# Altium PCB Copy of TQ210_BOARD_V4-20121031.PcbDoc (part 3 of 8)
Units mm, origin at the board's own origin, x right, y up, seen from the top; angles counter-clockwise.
Board outline 191.2 x 131.27 mm, 2 copper layers (TopLayer, BottomLayer); 362 components, 455 nets, 1594 pads, 630 vias.
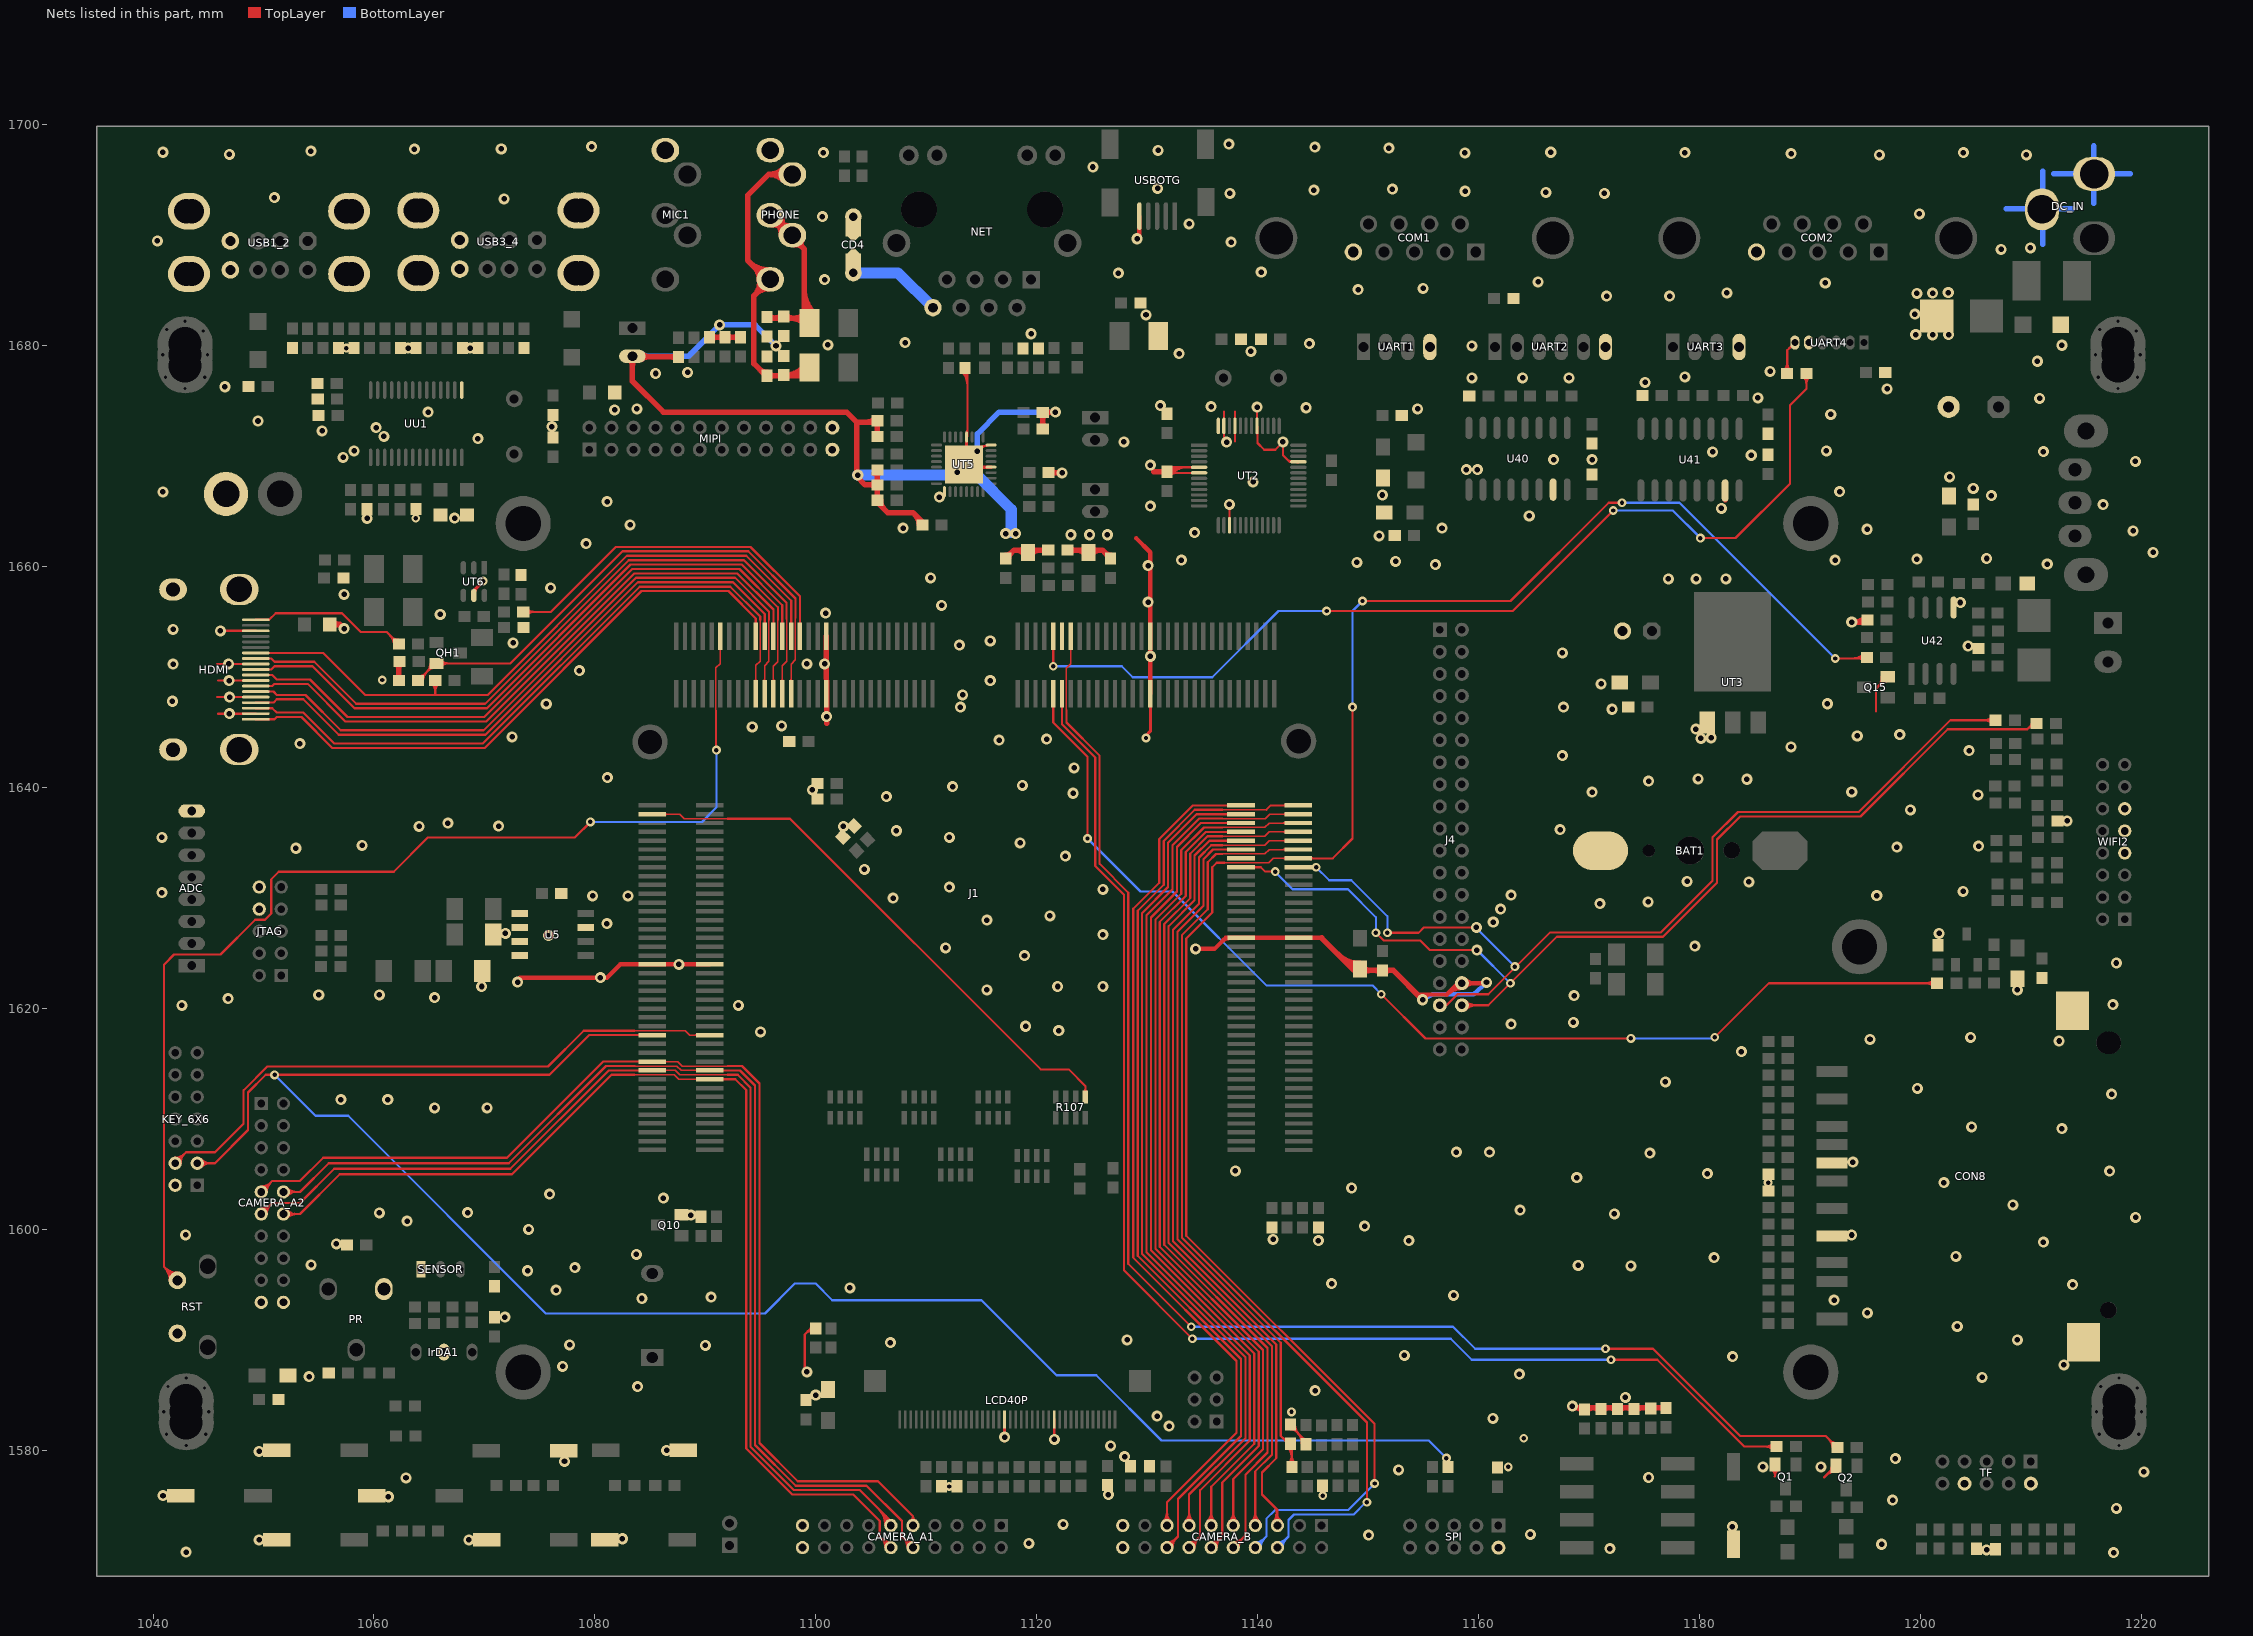
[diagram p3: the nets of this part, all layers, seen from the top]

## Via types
v1: diameter 1, hole 0.5, TopLayer to BottomLayer, 458 vias
v2: diameter 0.8, hole 0.4, TopLayer to BottomLayer, 172 vias

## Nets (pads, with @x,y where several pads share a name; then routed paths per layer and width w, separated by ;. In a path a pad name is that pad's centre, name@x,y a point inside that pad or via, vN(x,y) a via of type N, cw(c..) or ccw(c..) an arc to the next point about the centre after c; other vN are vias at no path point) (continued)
CAMDATA4: CAMERA_A1.12 CAMERA_A2.12 J1.18 | length 103.8
  TopLayer w0.135: 1083.6,1614 1087.2,1614 1087.6,1613.6 J1.18@1090.4,1613.6
  TopLayer w0.2: CAMERA_A2.12@1051.8,1601.4 1053.3,1601.4 1056.9,1605 1072.5,1605 1081.5,1614 1083.6,1614 ; CAMERA_A2.12@1052.012,1601.188 cw(c1052.524,1600.676) 1052.524,1601.4 cw(c1052.524,1602.124) CAMERA_A2.12@1052.012,1601.612 ; CAMERA_A2.12@1052.154,1601.046 cw(c1053.007,1600.193) 1053.007,1601.4 cw(c1053.007,1602.607) CAMERA_A2.12@1052.154,1601.754 ; J1.18@1090.4,1613.6 1092.719,1613.6 1093.7,1612.619 1093.7,1580.163 1097.863,1576 1103.4,1576 1105.8,1573.6 1105.8,1572.2 CAMERA_A1.12@1106.8,1571.2 ; CAMERA_A1.12@1106.3,1571.2 ccw(c1105.093,1571.2) 1105.946,1572.054 ccw(c1106.8,1572.907) CAMERA_A1.12@1106.8,1571.7 ; CAMERA_A1.12@1106.5,1571.2 ccw(c1105.776,1571.2) 1106.288,1571.712 ccw(c1106.8,1572.224) CAMERA_A1.12@1106.8,1571.5
CAMDATA5: CAMERA_A1.11 CAMERA_A2.11 J1.19 | length 105.7
  TopLayer w0.135: J1.19@1085.2,1614.4 1087.3,1614.4 1087.7,1614 1092,1614
  TopLayer w0.2: CAMERA_A2.11@1049.8,1601.4 1050.8,1602.4 1053.3,1602.4 1056.4,1605.5 1072.35,1605.5 1081.25,1614.4 J1.19@1085.2,1614.4 ; CAMERA_A2.11@1049.8,1601.7 ccw(c1049.8,1602.424) 1050.312,1601.912 ccw(c1050.824,1601.4) CAMERA_A2.11@1050.1,1601.4 ; CAMERA_A2.11@1049.8,1601.9 ccw(c1049.8,1603.107) 1050.654,1602.254 ccw(c1051.507,1601.4) CAMERA_A2.11@1050.3,1601.4 ; 1092,1614 1092.929,1614 1094.1,1612.829 1094.1,1580.328 1098.028,1576.4 1104,1576.4 1106.8,1573.6 CAMERA_A1.11@1106.8,1573.2 ; 1105.664,1574.736 cw(c1104.127,1573.2) CAMERA_A1.11@1106.3,1573.2 ; 1106.005,1574.395 cw(c1104.81,1573.2) CAMERA_A1.11@1106.5,1573.2 ; 1106.346,1574.054 cw(c1105.493,1573.2) CAMERA_A1.11@1106.7,1573.2
CAMDATA6: CAMERA_A1.10 CAMERA_A2.10 J1.20 | length 105.7
  TopLayer w0.135: 1083.6,1614.8 1087.4,1614.8 1087.8,1614.4 J1.20@1090.4,1614.4
  TopLayer w0.2: CAMERA_A2.10@1051.8,1603.4 1053.3,1603.4 1055.9,1606 1072.2,1606 1081,1614.8 1083.6,1614.8 ; CAMERA_A2.10@1052.012,1603.188 cw(c1052.524,1602.676) 1052.524,1603.4 cw(c1052.524,1604.124) CAMERA_A2.10@1052.012,1603.612 ; CAMERA_A2.10@1052.154,1603.046 cw(c1053.007,1602.193) 1053.007,1603.4 cw(c1053.007,1604.607) CAMERA_A2.10@1052.154,1603.754 ; J1.20@1090.4,1614.4 1093.138,1614.4 1094.5,1613.038 1094.5,1580.494 1098.194,1576.8 1104.6,1576.8 1107.8,1573.6 1107.8,1572.2 CAMERA_A1.10@1108.8,1571.2 ; CAMERA_A1.10@1108.3,1571.2 ccw(c1107.093,1571.2) 1107.946,1572.054 ccw(c1108.8,1572.907) CAMERA_A1.10@1108.8,1571.7 ; CAMERA_A1.10@1108.5,1571.2 ccw(c1107.776,1571.2) 1108.288,1571.712 ccw(c1108.8,1572.224) CAMERA_A1.10@1108.8,1571.5
CAMDATA7: CAMERA_A1.9 CAMERA_A2.9 J1.21 | length 104.8
  TopLayer w0.135: J1.21@1085.2,1615.2 1087.5,1615.2 1087.9,1614.8 1092,1614.8
  TopLayer w0.2: CAMERA_A2.9@1049.8,1603.4 1050.8,1604.4 1053.3,1604.4 1055.4,1606.5 1072.05,1606.5 1080.75,1615.2 J1.21@1085.2,1615.2 ; CAMERA_A2.9@1049.8,1603.7 ccw(c1049.8,1604.424) 1050.312,1603.912 ccw(c1050.824,1603.4) CAMERA_A2.9@1050.1,1603.4 ; CAMERA_A2.9@1049.8,1603.9 ccw(c1049.8,1605.107) 1050.654,1604.254 ccw(c1051.507,1603.4) CAMERA_A2.9@1050.3,1603.4 ; 1092,1614.8 1093.323,1614.8 1094.9,1613.223 1094.9,1580.66 1098.36,1577.2 1105.634,1577.2 1108.8,1574.034 ; CAMERA_A1.9@1108.564,1573.641 ccw(c1108.354,1574.034) 1108.8,1574.034 ; CAMERA_A1.9@1108.8,1573.2 1108.8,1574.034 ; CAMERA_A1.9@1109.036,1573.641 cw(c1109.246,1574.034) 1108.8,1574.034
DAC_OUT0: J1.109 RT64.1 | length 34.5
  TopLayer w0.2: RT64.1@1073.51,1655.911 1076,1655.911 1081.889,1661.8 1094.1,1661.8 1098.575,1657.325 J1.109@1098.575,1653.687 ; RT64.1@1073.843,1655.629 cw(c1074.526,1654.946) 1074.526,1655.911 cw(c1074.526,1656.877) RT64.1@1073.843,1656.194
EXT_NRESET: J1.91 RST.2 | length 107
  TopLayer w0.135: 1090.965,1647.016 1090.965,1650.837 1091.365,1651.236 J1.91@1091.365,1653.697
  TopLayer w0.2: RST.2@1041.5,1595.4 ccw(c1039.81,1595.4) 1041.005,1596.595 ccw(c1042.2,1597.79) RST.2@1042.2,1596.1 ; RST.2@1041.7,1595.4 ccw(c1040.493,1595.4) 1041.346,1596.254 ccw(c1042.2,1597.107) RST.2@1042.2,1595.9 ; RST.2@1042.2,1595.4 1041,1596.6 1041,1624 1041.9,1624.9 1046.1,1624.9 1049.238,1628.038 1050.138,1628.038 1050.7,1628.6 1050.7,1631.7 1051.385,1632.385 1061.785,1632.385 1064.9,1635.5 1078.2,1635.5 v2(1079.6,1636.9) ; v2@1090.981,1643.419 1090.981,1647
  BottomLayer w0.2: v2(1079.6,1636.9) 1089.703,1636.9 1091,1638.197 v2(1091,1643.4)
GND: ADC.8 BAT1.2 C1.2 C3.2 C5.2 C6.2 C8.2 C9.2 C10.2 C11.2 C12.2 C15.2 C17.2 C21.2 C22.2 C23.2 C101.2 C102.2 C105.2 C106.2 C107.2 C111.2 C201.2 C202.2 C203.2 C205.2 C207.1 C208.1 C210.2 C211.1 C212.1 C403.2 C404.2 C405.2 C413.2 C414.2 C415.2 C423.1 C501.2 C513.2 C517.2 C518.2 CAMERA_A1.19 CAMERA_A1.20 CAMERA_A2.19 CAMERA_A2.20 CAMERA_B.19 CAMERA_B.20 CD1.2 CD2.2 CD4.2 CL1.2 CL2.2 CL3.2 CL4.2 CL5.2 CM1.2 CM2.2 CM3.2 CM4.2 CMB1.2 CMB2.2 COM1.5 COM2.5 CON8.3 CON8.6 CON8.13 CON8.14 CS1.2 CS2.2 CT6.1 CU1.2 CU2.2 CU3.1 CU4.2 CU5.2 CU6.2 CU7.2 CU10.1 CU11.1 CV1.2 CW1.2 CW2.1 CW4.1 CW5.2 D6.1 D8.1 D101.1 DC_IN.2 DC_IN.3 HDMI.2 HDMI.5 HDMI.8 HDMI.11 HDMI.17 HDMI.20 HDMI.21 HDMI.22 HDMI.23 IrDA1.2 J1.43 J1.44 J1.115 J1.116 J1.171 J1.172 J1.231 J1.232 J4.34 JTAG.8 JTAG.10 KEY1.2 KEY2.2 KEY3.2 KEY4.2 KEY5.2 KEY6.2 KEY7.2 KEY8.2 KEY_6X6.2 KEYON.2 L502.1 LCD40P.20 LCD40P.29 MIPI.23 MIPI.24 POWER.2 PR.1 Q1.E Q2.E Q10.E Q15.E R31.2 R204.2 R424.2 RF2.2 RH13.1 RH14.2 RM6.2 RM21.1 RMB6.2 RMB21.1 RO1.1 RO2.2 RO3.2 RO4.2 RO5.1 RO6.1 RST.1 RT1.2 RT3.1 RT63.2 RT65.2 RU3.1 RU4.1 RU7.1 RU8.1 RU11.1 RU12.1 RU15.1 RU16.1 RU17.2 RU21.2 SENSOR.1 SPI.2 TF.2 TF.8 TVOUT.2 U5.1 U5.2 U5.3 U5.4 U5.7 U40.15 U41.15 U42.5 UART1.4 UART2.6 UART3.4 UART4.5 USB1_2.4 USB1_2.8 USB1_2.9 USB1_2.10 USB1_2.11 USB1_2.12 USB3_4.4 USB3_4.8 USB3_4.9 USB3_4.10 USB3_4.11 USB3_4.12 USBOTG.5 UT2.5 UT2.6 UT2.15 UT2.33 UT2.41 UT2.45 UT2.47 UT2.48 UT3.1 UT5.9 UT6.5 UU1.1 WIFI2.7 WIFI2.9 WIFI2.11 | length 238.1
  TopLayer w0.2: 1045.8,1648.2 HDMI.5@1049.3,1648.2 ; 1045.8,1651.2 HDMI.11@1049.3,1651.2 ; v1@1045.8,1654.2 HDMI.17@1049.3,1654.2 ; 1045.9,1646.7 HDMI.2@1049.3,1646.7 ; 1045.9,1649.7 HDMI.8@1049.3,1649.7 ; RH13.1@1062.252,1651.359 RH13.1@1062.298,1651.405 ; UT6.5@1069.045,1657.845 UT6.5@1069.045,1657.412 UT6.5@1069.1,1657.467 ; 1099.015,1590.515 cw(c1099.759,1589.772) R31.2@1099.961,1590.804 ; v1(1099.2,1587.1) 1099,1587.3 1099,1590.5 1099.55,1591.05 R31.2@1100,1591.05 ; 1099.281,1590.781 cw(c1099.846,1590.216) R31.2@1100,1591 ; 1100.975,1645.825 1101,1645.8 ; C211.1@1131.659,1668.791 cw(c1132.172,1668.278) C211.1@1132.172,1669.004 ; C211.1@1131.8,1668.65 cw(c1132.655,1667.795) 1132.655,1669.004 ; C211.1@1131.941,1668.509 cw(c1133.138,1667.312) 1133.138,1669.004 ; C211.1@1131.941,1668.691 ccw(c1132.393,1669.143) 1132.393,1668.504 ; C211.1@1132,1669 1132.004,1669.004 UT2.5@1134.703,1669.004 ; C211.1@1132.004,1668.504 UT2.6@1134.703,1668.504 ; C211.1@1132.083,1668.267 cw(c1132.655,1667.695) 1132.655,1668.504 ; C211.1@1132.083,1668.367 cw(c1133.621,1666.829) 1133.621,1669.004 ; C211.1@1132.083,1668.833 ccw(c1132.876,1669.626) 1132.876,1668.504 ; v1@1136.953,1671.6 1136.953,1674.055 ; UT2.15@1137.453,1663.754 v1(1137.453,1665.653) ; 1137.953,1671.343 1137.953,1674.045 ; UT2.41@1139.918,1672.119 cw(c1139.712,1671.913) 1140.003,1671.913 ; UT2.41@1139.953,1672.754 v1(1139.953,1674.453) v1@1140.1,1674.6 ; UT2.41@1140.003,1672.704 1140.003,1671.2 1140.603,1670.6 1141.6,1670.6 v1(1142.3,1671.3) 1142.3,1670.1 1142.896,1669.504 UT2.33@1143.6,1669.504 ; 1142.664,1669.736 ccw(c1143.103,1670.176) UT2.33@1143.103,1669.554 ; RMB6.2@1143,1581.9 cw(c1143,1581.135) 1143.541,1581.676 ; RMB6.2@1143,1582.35 1143,1582.217 C8.2@1144.448,1580.769 ; RMB6.2@1143.2,1582.3 ccw(c1143.884,1582.3) RMB6.2@1143.4,1581.817 ; RMB6.2@1143.4,1582.3 ccw(c1144.567,1582.3) 1143.742,1581.475 ; 1143.562,1581.655 cw(c1142.518,1580.611) C8.2@1143.995,1580.611 ; 1143.904,1581.313 cw(c1143.201,1580.611) C8.2@1144.195,1580.611 ; 1144.073,1581.144 ccw(c1144.395,1581.465) C8.2@1144.395,1581.011 ; J4.34@1158.1,1622.3 J4.34@1158.5,1622.3 ; v1(1160.729,1622.374) v1@1160.729,1622.629 ; Q1.E@1186.577,1578.272 cw(c1186.008,1577.649) 1186.852,1577.649 ; 1186.832,1577.629 1186.852,1577.649 ; Q1.E@1186.852,1578.7 1186.852,1577.649 ; Q1.E@1187.127,1578.272 ccw(c1187.695,1577.649) 1186.852,1577.649 ; 1191.289,1577.538 Q2.E@1192.36,1578.609 ; 1191.447,1577.696 cw(c1192.36,1576.782) Q2.E@1192.36,1578.074 ; 1191.754,1578.002 ccw(c1191.274,1578.482) Q2.E@1191.952,1578.482 ; 1191.788,1578.037 cw(c1192.36,1577.465) Q2.E@1192.36,1578.274 ; 1196,1646.9 1196,1648.981 Q15.E@1197.059,1650.04 ; 1196.146,1649.126 ccw(c1195.232,1650.04) Q15.E@1196.524,1650.04 ; 1196.452,1649.433 cw(c1196.932,1648.953) Q15.E@1196.932,1649.632 ; 1196.487,1649.468 ccw(c1195.915,1650.04) Q15.E@1196.724,1650.04
  TopLayer w0.25: v1@1117.1,1580.85 LCD40P.20@1117.1,1583.3 ; v1@1121.6,1581.1 LCD40P.29@1121.6,1582.8
  TopLayer w0.3: UT6.5@1069.045,1657.845 v2(1069.9,1658.7) ; UT6.5@1069.145,1657.762 cw(c1069.585,1657.762) 1069.274,1658.074 ; v2@1129.9,1644.7 1130.306,1645.106 J1.172@1130.306,1648.495 ; UT2.33@1143.6,1669.504 UT2.33@1143.703,1669.504
  TopLayer w0.4: v1@1073.2,1622.8 1081.1,1622.8 1082.3,1624 J1.44@1090.4,1624 ; 1129,1662.6 1130.296,1661.304 1130.296,1655.322 J1.172@1130.296,1648.506 ; v1@1129.3,1689.9 USBOTG.5@1129.3,1691.75 ; v1(1134.4,1625.4) 1136.1,1625.4 1137.095,1626.395 J1.231@1143.715,1626.395 1145.805,1626.395 ; 1136.833,1626.133 cw(c1137.465,1625.501) 1137.465,1626.395 ccw(c1137.372,1625.747) 1136.91,1626.21 ; 1154.527,1621.275 1157.127,1621.275 ; v1(1154.95,1620.8) 1155.425,1621.275 ; 1157.106,1621.244 1158.163,1622.3 v1@1160.7,1622.3 ; 1157.181,1621.319 cw(c1158.5,1620) J4.34@1158.5,1621.865 ; 1157.864,1622.002 cw(c1158.5,1621.366) J4.34@1158.5,1622.265 ; J4.34@1158.808,1621.992 cw(c1159.55,1621.25) 1159.55,1622.3 cw(c1159.55,1623.35) J4.34@1158.808,1622.608
  TopLayer w0.5: CU7.2@1056.004,1654.779 1056.921,1654.779 v1(1057.3,1654.4) ; CU7.2@1056.252,1654.531 cw(c1056.849,1653.934) 1056.849,1654.779 cw(c1056.849,1655.624) CU7.2@1056.252,1655.026 ; RH13.1@1062.071,1651.229 cw(c1061.636,1650.793) 1062.252,1650.793 ; RH14.2@1062.075,1649.871 ccw(c1061.648,1650.298) 1062.252,1650.298 ccw(c1062.855,1650.298) RH14.2@1062.429,1649.871 ; RH14.2@1062.252,1649.695 RH13.1@1062.252,1651.359 ; 1062.252,1650.811 cw(c1062.843,1650.811) RH13.1@1062.425,1651.229 ; J1.115@1100.965,1653.697 1100.975,1645.825 ; C513.2@1121.078,1668.524 v1@1122.276,1668.524 ; C513.2@1121.305,1668.347 cw(c1121.731,1667.92) 1121.731,1668.524 cw(c1121.731,1669.128) C513.2@1121.305,1668.701 ; L502.1@1122.8,1661.5 1125.95,1661.5 C518.2@1126.7,1660.75 ; L502.1@1123.027,1661.323 cw(c1123.454,1660.896) 1123.454,1661.5 cw(c1123.454,1662.104) L502.1@1123.027,1661.677 ; 1123.58,1661.5 cw(c1123.58,1660.301) C517.2@1124.428,1661.149 ; 1123.961,1661.5 ccw(c1123.961,1662.16) C517.2@1124.428,1661.693 ; C517.2@1124.972,1661.149 cw(c1125.82,1660.301) 1125.82,1661.5 ; C517.2@1124.972,1661.693 ccw(c1125.439,1662.16) 1125.439,1661.5 ; 1126.188,1661.262 ccw(c1126.7,1661.774) C518.2@1126.7,1661.05 ; C518.2@1126.309,1661.141 cw(c1125.967,1660.8) C518.2@1126.45,1660.8 ; 1130.6,1668.597 1130.603,1668.6 C211.1@1131.8,1668.6 ; 1145.805,1626.395 1148.75,1623.45 1152.3,1623.45 v1(1154.95,1620.8) ; 1147.295,1624.905 ccw(c1149.263,1626.874) C21.2@1149.263,1624.09 ; 1148.148,1624.052 ccw(c1149.263,1625.166) C21.2@1149.263,1623.59 ; C21.2@1149.535,1623.179 cw(c1150.19,1622.524) 1150.19,1623.45 ; C21.2@1149.535,1623.723 ccw(c1150.195,1624.383) 1150.195,1623.45 ; CMB2.2@1151.123,1623.273 ccw(c1150.696,1622.846) 1150.696,1623.45 ccw(c1150.696,1624.054) CMB2.2@1151.123,1623.627 ; CMB2.2@1151.477,1623.273 cw(c1151.904,1622.846) 1151.904,1623.45 cw(c1151.904,1624.054) CMB2.2@1151.477,1623.627 ; v1@1168.324,1583.868 1168.342,1583.85 RT1.2@1177,1583.85 ; v1@1168.816,1583.85 cw(c1168.816,1582.96) RO1.1@1169.445,1583.589 ; RO1.1@1169.799,1583.589 cw(c1170.428,1582.96) 1170.428,1583.85 ; 1170.376,1583.85 cw(c1170.376,1583.076) RO2.2@1170.923,1583.623 ; BAT1.2@1171,1632.9 BAT1.2@1171,1634.5 ; RO2.2@1171.277,1583.623 cw(c1171.824,1583.076) 1171.824,1583.85 ; 1171.876,1583.85 cw(c1171.876,1583.076) RO3.2@1172.423,1583.623 ; RO3.2@1172.777,1583.623 cw(c1173.324,1583.076) 1173.324,1583.85 ; 1173.376,1583.85 cw(c1173.376,1583.076) RO4.2@1173.923,1583.623 ; RO4.2@1174.277,1583.623 cw(c1174.824,1583.076) 1174.824,1583.85 ; C1.2@1175.423,1583.673 ccw(c1174.996,1583.246) 1174.996,1583.85 ccw(c1174.996,1584.454) C1.2@1175.423,1584.027 ; C1.2@1175.777,1583.673 cw(c1176.204,1583.246) 1176.204,1583.85 cw(c1176.204,1584.454) C1.2@1175.777,1584.027 ; RT1.2@1176.823,1583.673 ccw(c1176.396,1583.246) 1176.396,1583.85 ccw(c1176.396,1584.454) RT1.2@1176.823,1584.027 ; U41.15@1182.33,1666.07 U41.15@1182.33,1667.112 ; v1(1193.8,1655) 1195.022,1655 C423.1@1195.21,1655.187 ; v1@1194.104,1655 ccw(c1194.104,1656.243) C423.1@1194.983,1655.364
  BottomLayer w0.2: v1@1160.729,1622.357 v1(1160.729,1622.374)
  BottomLayer w0.4: v1(1154.95,1620.8) 1155.878,1621.282 1159.578,1621.282 v1@1160.729,1622.357
  BottomLayer w0.5: 1207.798,1692.4 1213.8,1692.4 ; 1211.098,1689.2 1211.098,1695.8 ; 1212.1,1695.597 1219,1695.597 ; 1215.7,1692.897 1215.7,1698.098
  other v1: 1217.5,1570.75 1043,1570.787 1206,1571 1171.9,1571.1 1196.5,1571.5 1119.302,1571.574 1049.6,1571.9 1068.6,1571.9 1082.5,1572 1150.061,1572.336 1164.7,1572.4 1183,1573.1 1122.4,1573.3 1217.75,1574.75 1197.5,1575.5 1061.3,1575.8 1040.9,1575.9 1126.5,1576 1062.9,1577.5 1175.398,1577.543 1220.241,1578.051 1152.779,1578.229 1185.75,1578.5 1191,1578.5 1077.25,1579 1197.75,1579.25 1127.97,1579.435 1049.6,1579.9 1086.5,1580 1126.7,1580.4 1121.613,1580.997 1117.1,1581.2 1132,1582.2 1161.298,1582.9 1130.9,1583.1 1168.5,1584 1173.3,1584.8 1100,1585 1145.21,1585.417 1083.869,1585.773 1205.6,1586.6 1054.125,1586.687 1163.7,1586.9 1077.087,1587.597 1213,1587.75 1183.005,1588.491 1153.3,1588.6 1090,1589.5 1077.722,1589.557 1106.75,1589.75 1128.2,1590 1208.8,1589.997 1203.35,1591.234 1071.855,1592.072 1195.222,1592.453 1192.2,1593.6 1084.25,1593.75 1090.524,1593.875 1157.757,1594.028 1076.5,1594.5 1103.098,1594.714 1213.798,1595 1146.7,1595.1 1073.912,1596.263 1078.198,1596.542 1173.8,1596.7 1169.035,1596.746 1054.303,1596.796 1181.329,1597.457 1203.223,1597.558 1083.767,1597.736 1056.6,1598.7 1211.148,1598.854 1145.5,1599 1153.7,1598.997 1141.4,1599.1 1193.795,1599.5 1042.949,1599.514 1074,1600 1149.7,1600.3 1063,1600.75 1219.5,1601.097 1088.7,1601.3 1172.312,1601.419 1060.5,1601.5 1068.476,1601.521 1163.777,1601.749 1208.38,1602.232 1086.206,1602.842 1075.9,1603.2 1148.512,1603.756 1202.131,1604.239 1168.9,1604.7 1180.719,1605.051 1217.143,1605.28 1138,1605.3 1193.9,1606.1 1175.512,1606.906 1158,1607 1161,1607 1212.825,1609.141 1204.646,1609.293 1065.5,1611 1070.25,1611 1057,1611.75 1061.25,1611.75 1217.32,1612.265 1199.744,1612.773 1176.934,1613.357 1183.8,1616.1 1212.571,1617.066 1195.451,1617.218 1204.57,1617.396 1094.998,1617.9 1122,1618 1119,1618.4 1162.964,1618.59 1168.603,1618.742 1042.6,1620.297 1093,1620.297 1217.447,1620.368 1046.8,1620.897 1065.5,1621 1168.654,1621.18 1055,1621.25 1060.5,1621.25 1115.5,1621.7 1208.8,1621.7 1069.75,1622 1121.9,1622 1126,1622 1073,1622.397 1080.5,1622.8 1087.6,1624 1217.752,1624.127 1118.9,1624.8 1111.75,1625.5 1179.601,1625.651 1075.8,1626.6 1126,1626.7 1071.9,1626.8 1201.7,1626.8 1081.098,1627.697 1161.339,1627.835 1115.5,1628 1121.2,1628.397 1162,1628.997 1170.991,1629.512 1175.36,1629.664 1107,1630 1079.8,1630.2 1083,1630.2 1196.061,1630.223 1162.964,1630.274 1040.8,1630.497 1203.884,1630.604 1126,1630.8 1112.1,1631 1184.478,1631.467 1178.89,1631.518 1104.4,1632.6 1122.6,1633.8 1052.932,1634.515 1197.889,1634.617 1205.281,1634.719 1058.926,1634.769 1118.5,1634.997 1040.8,1635.5 1112.098,1635.5 1107.298,1636.1 1167.4,1636.197 1064.098,1636.5 1102.5,1636.5 1071.296,1636.522 1066.7,1636.797 1213.3,1637 1199.1,1638 1106.4,1639.197 1205.23,1639.341 1123.298,1639.497 1170.298,1639.6 1193.8,1639.621 1099.7,1639.8 1112.4,1640.097 1118.698,1640.2 1175.398,1640.6 1184.3,1640.764 1179.898,1640.8 1081.126,1640.916 1123.4,1641.8 1167.598,1642.9 1204.417,1643.355 1188.298,1643.7 1053.3,1643.997 1116.6,1644.3 1120.9,1644.4 1180.135,1644.472 1181.075,1644.523 1072.5,1644.597 1194.298,1644.7 1198.143,1644.802 1179.678,1645.31 1094.25,1645.5 1096.9,1645.6 1100.975,1646.428 1046.912,1646.7 1172.098,1647.1 1113.1,1647.297 1167.7,1647.297 1075.6,1647.597 1191.598,1647.6 1041.756,1647.825 1046.937,1648.2 1113.3,1648.4 1171.1,1649.397 1046.886,1649.7 1115.8,1649.697 1078.6,1650.597 1041.806,1651.178 1046.836,1651.2 1099.2,1651.2 1100.8,1651.2 1130.296,1651.9 1167.598,1652.2 1204.341,1652.829 1112.998,1652.9 1072.591,1653.108 1115.8,1653.3 1046.099,1654.2 1041.806,1654.327 1066,1655.697 1100.9,1655.8 1111.4,1656.5 1203.63,1656.766 1130.098,1656.8 1057.3,1657.497 1076,1658.097 1177.2,1658.9 1179.7,1658.9 1182.395,1658.899 1110.4,1658.997 1130.098,1660.1 1156.1,1660.197 1211.5,1660.25 1148.998,1660.4 1152.5,1660.497 1133.098,1660.6 1192.3,1660.6 1199.7,1660.7 1206,1660.75 1221.08,1661.312 1079.2,1662.1 1151,1662.8 1123.1,1662.9 1124.8,1662.9 1126.4,1662.9 1134.298,1663.1 1219.276,1663.243 1195.198,1663.4 1107.9,1663.5 1156.7,1663.497 1083.2,1663.797 1059.384,1664.376 1067.298,1664.397 1164.598,1664.6 1182,1665.297 1130.3,1665.5 1216.558,1665.63 1081.1,1665.897 1111.2,1666.3 1206.449,1666.443 1151.3,1666.5 1040.892,1666.773 1192.7,1666.797 1204.798,1667.104 1139.6,1667.697 1202.665,1668.145 1122.3,1668.5 1158.898,1668.8 1159.9,1668.8 1130.3,1669.197 1219.479,1669.542 1166.8,1669.7 1170.3,1669.7 1057.2,1669.9 1184.7,1670.1 1181.2,1670.4 1211.148,1670.431 1058.2,1670.5 1191.5,1670.5 1127.9,1671.3 1137.2,1671.297 1069.4,1671.597 1060.9,1671.8 1055.3,1672.3 1060.198,1672.6 1076.1,1672.7 1049.5,1673.2 1191.898,1673.8 1064.9,1673.997 1081.798,1674.2 1083.8,1674.297 1154.5,1674.3 1144.4,1674.4 1135.798,1674.5 1131.2,1674.6 1210.818,1675.257 1185.298,1675.3 1197,1676.1 1046.5,1676.3 1175.1,1676.7 1159.4,1677.1 1163.998,1677.1 1168.198,1677.1 1178.698,1677.2 1085.5,1677.5 1088.4,1677.6 1186.4,1677.7 1210.615,1678.61 1132.9,1679.3 1139.4,1679.5 1063.1,1679.8 1068.7,1679.8 1159.4,1679.997 1212.825,1680.058 1101.1,1680.1 1144.7,1680.2 1108.1,1680.297 1201.115,1680.997 1199.591,1681.023 1202.563,1681.023 1119.5,1681.1 1129.9,1682.8 1199.515,1682.877 1171.6,1684.497 1177.3,1684.497 1199.693,1684.757 1201.115,1684.782 1182.5,1684.797 1202.538,1684.833 1149.1,1685.097 1154.998,1685.2 1191.4,1685.697 1165.4,1685.8 1100.8,1685.997 1127.4,1686.597 1140.333,1686.687 1207.313,1688.744 1209.98,1688.871 1137.6,1689.4 1040.4,1689.5 1129.1,1689.7 1133.805,1691.056 1100.6,1691.697 1199.921,1691.945 1071.778,1693.316 1050.99,1693.42 1137.5,1693.8 1171.4,1693.8 1166.1,1693.9 1158.799,1694.002 1145.1,1694.1 1152.2,1694.2 1130.96,1694.256 1125.1,1696.197 1196.3,1697.3 1209.6,1697.3 1046.901,1697.331 1188.3,1697.4 1158.773,1697.482 1100.698,1697.5 1178.7,1697.5 1203.9,1697.5 1040.892,1697.533 1166.546,1697.533 1054.292,1697.636 1131,1697.7 1063.65,1697.812 1071.524,1697.838 1151.9,1697.9 1145.2,1698 1079.703,1698.041 1137.412,1698.269
  other v2: 1145.9,1575.9 1112.088,1576.73 1162.7,1578.5 1164.1,1581.1 1143.076,1583.487 1186.231,1604.239 1129.9,1644.5 1060.75,1649.75 1063.778,1664.402 1057.5,1679.8
GND_AC97: C503.2 C504.2 C505.2 C506.1 C509.2 C510.2 C511.2 C512.2 C519.2 C520.2 C521.2 C522.2 C523.2 C525.2 C526.2 C527.2 L502.2 MIC1.1 MIC2.2 PHONE.1 R502.1 R503.1 R506.2 UT5.20 UT5.24 UT5.28 UT5.33 | length 143.3
  TopLayer w0.2: C506.1@1113.217,1677.667 cw(c1111.984,1676.434) 1113.728,1676.434 ; C506.1@1113.359,1677.809 cw(c1112.467,1676.917) 1113.728,1676.917 ; C506.1@1113.5,1677.95 cw(c1112.95,1677.4) 1113.728,1677.4 ; UT5.28@1113.635,1672.142 ccw(c1113.411,1672.365) 1113.728,1672.365 ; UT5.28@1113.653,1671.749 1113.728,1671.824 1113.728,1677.672 C506.1@1113.7,1677.7 ; UT5.33@1114.967,1669.02 UT5.33@1114.971,1669.024
  TopLayer w0.25: UT5.33@1113.285,1669.321 cw(c1115.517,1668.583) UT5.33@1114.996,1670.875 ; UT5.33@1113.523,1669.243 cw(c1116.008,1668.42) UT5.24@1115.428,1670.973 ; UT5.33@1114.992,1670.874 UT5.24@1115.551,1671.001
  TopLayer w0.3: UT5.33@1113.646,1670.747 UT5.28@1113.653,1671.749 ; UT5.33@1114.971,1669.024 UT5.20@1115.878,1669.024
  TopLayer w0.5: MIC2.2@1083.153,1678.813 cw(c1082.555,1678.215) 1083.4,1678.215 cw(c1084.245,1678.215) MIC2.2@1083.647,1678.813 ; MIC2.2@1083.4,1679.06 1083.4,1676.8 1086.2,1674 1102.8,1674 1103.7,1673.1 ; MIC2.2@1083.5,1679 1087.56,1679 C525.2@1087.574,1678.986 ; MIC2.2@1084.247,1678.813 cw(c1084.7,1678.36) 1084.7,1679 ; MIC2.2@1084.247,1679.307 ccw(c1084.99,1680.05) 1084.99,1679 ; 1086.936,1679 cw(c1086.936,1678.347) C525.2@1087.397,1678.809 ; 1087.005,1679 ccw(c1087.005,1679.554) C525.2@1087.397,1679.162 ; 1091.117,1680.783 C511.2@1093.181,1680.783 ; C509.2@1091.604,1680.607 ccw(c1091.177,1680.18) 1091.177,1680.783 ccw(c1091.177,1681.387) C509.2@1091.604,1680.96 ; C509.2@1091.958,1680.607 cw(c1092.385,1680.18) 1092.385,1680.783 cw(c1092.385,1681.387) C509.2@1091.958,1680.96 ; C511.2@1093.004,1680.607 ccw(c1092.577,1680.18) 1092.577,1680.783 ccw(c1092.577,1681.387) C511.2@1093.004,1680.96 ; 1104.625,1673.1 ccw(c1104.625,1674.127) C526.2@1105.351,1673.401 ; C504.2@1105.286,1668.486 C504.2@1105.579,1668.778 ; C503.2@1105.351,1667.247 ccw(c1104.924,1666.82) 1104.924,1667.424 ccw(c1104.924,1668.028) C503.2@1105.351,1667.601 ; C527.2@1105.401,1666.201 ccw(c1104.974,1666.628) 1105.578,1666.628 ccw(c1106.181,1666.628) C527.2@1105.755,1666.201 ; C503.2@1105.401,1667.247 cw(c1104.974,1666.82) 1105.578,1666.82 cw(c1106.181,1666.82) C503.2@1105.755,1667.247 ; C503.2@1105.401,1667.601 ccw(c1104.974,1668.028) 1105.578,1668.028 ccw(c1106.181,1668.028) C503.2@1105.755,1667.601 ; C504.2@1105.402,1668.602 cw(c1104.977,1668.177) 1105.578,1668.177 ; C505.2@1105.402,1671.955 ccw(c1104.977,1672.38) 1105.578,1672.38 ; C526.2@1105.401,1673.047 cw(c1104.974,1672.62) 1105.578,1672.62 cw(c1106.181,1672.62) C526.2@1105.755,1673.047 ; C503.2@1105.578,1667.424 1104.476,1667.424 1103.7,1668.2 1103.7,1673.1 ; 1105.578,1668.173 cw(c1106.184,1668.173) C504.2@1105.755,1668.602 ; C504.2@1105.579,1668.778 1105.578,1665.822 1106.5,1664.9 1108.8,1664.9 1109.65,1664.05 C520.2@1109.65,1663.8 ; C505.2@1105.578,1671.779 C526.2@1105.578,1673.224 ; 1105.578,1672.384 ccw(c1106.184,1672.384) C505.2@1105.755,1671.955 ; C526.2@1105.578,1673.1 1103.7,1673.1 ; C527.2@1105.878,1666.024 ccw(c1107.089,1666.024) 1106.233,1665.167 ; 1108.961,1664.739 cw(c1108.022,1663.8) C520.2@1109.35,1663.8 ; C521.2@1117.2,1660.75 1117.95,1661.5 L502.2@1121.05,1661.5 ; C521.2@1117.2,1661.05 ccw(c1117.2,1661.774) 1117.712,1661.262 ; C521.2@1117.45,1660.8 cw(c1117.933,1660.8) C521.2@1117.591,1661.141 ; 1118.08,1661.5 cw(c1118.08,1660.301) C519.2@1118.928,1661.149 ; 1118.461,1661.5 ccw(c1118.461,1662.16) C519.2@1118.928,1661.693 ; C519.2@1119.472,1661.149 cw(c1120.32,1660.301) 1120.32,1661.5 ; C519.2@1119.472,1661.693 ccw(c1119.939,1662.16) 1119.939,1661.5 ; C512.2@1120.381,1672.65 ccw(c1119.954,1673.077) 1120.558,1673.077 ccw(c1121.161,1673.077) C512.2@1120.735,1672.65 ; C510.2@1120.381,1673.796 cw(c1119.954,1673.37) 1120.558,1673.37 cw(c1121.161,1673.37) C510.2@1120.735,1673.796 ; C512.2@1120.558,1672.473 C510.2@1120.558,1673.973 1120.585,1674 v1(1121.7,1674) ; C510.2@1120.785,1673.796 cw(c1121.276,1673.305) v1@1121.276,1674 ; C510.2@1120.785,1674.15 ccw(c1121.147,1674.512) 1121.147,1674 ; L502.2@1120.823,1661.323 ccw(c1120.396,1660.896) 1120.396,1661.5 ccw(c1120.396,1662.104) L502.2@1120.823,1661.677 ; 1090.985,1680.783 cw(c1090.985,1681.387) 1090.558,1680.96 ccw(c1090.985,1681.387) 1090.985,1680.783 ; 1090.985,1680.783 ccw(c1090.985,1680.18) 1090.558,1680.607 cw(c1090.985,1680.18) 1090.985,1680.783
  BottomLayer w0.5: MIC2.2@1083.4,1679.06 1088.46,1679.06 v1(1091.3,1681.9) 1094.5,1681.9 v1(1096.4,1680) ; MIC2.2@1084.247,1678.813 cw(c1084.845,1678.215) 1084.845,1679.06 cw(c1084.845,1679.905) MIC2.2@1084.247,1679.307 ; v1(1114.637,1670.467) 1114.637,1672.037 1116.6,1674 v1(1121.7,1674)
  BottomLayer w1: v1(1103.8,1668.3) 1114.6,1668.3 ; v1@1114.6,1670.4 1114.6,1668.3 ; v1@1117.7,1663.1 1117.7,1665.2 1114.6,1668.3
  other v1: 1117.2,1663 1118.1,1663 1112.808,1668.562
GND_CHASIS: CD4.1 NET.8 | length 8.5
  BottomLayer w1: CD4.1@1103.408,1686.605 1107.465,1686.605 NET.8@1110.61,1683.46
GPC1_0: J1.149 RN4.1 | length 91.8
  TopLayer w0.2: J1.149@1121.425,1652.585 cw(c1121.229,1652.389) 1121.506,1652.389 ; J1.149@1121.496,1653.811 J1.149@1121.496,1653.706 J1.149@1121.512,1653.722 ; v2(1121.5,1651) 1121.506,1651.006 J1.149@1121.506,1653.695 ; 1121.506,1652.439 cw(c1121.712,1652.439) J1.149@1121.566,1652.585 ; v2(1146.25,1656) 1163.1,1656 v2(1172.2,1665.1) ; v2(1180.1,1662.6) 1183.269,1662.6 1188.2,1667.531 1188.2,1674.631 1189.7,1676.131 RN4.1@1189.7,1677.5 ; RN4.1@1189.417,1677.217 cw(c1188.734,1676.534) 1189.7,1676.534 cw(c1190.666,1676.534) RN4.1@1189.983,1677.217
  BottomLayer w0.2: v2(1121.5,1651) 1127.7,1651 1128.7,1650 1135.9,1650 1141.9,1656 v2(1146.25,1656) ; v2(1172.2,1665.1) 1177.6,1665.1 v2(1180.1,1662.6)
GPC1_1: J1.150 RW19.1 | length 102.7
  TopLayer w0.2: J1.150@1121.425,1647.385 cw(c1121.229,1647.189) 1121.506,1647.189 ; 1121.506,1647.239 cw(c1121.712,1647.239) J1.150@1121.566,1647.385 ; J1.150@1121.506,1648.495 1121.506,1645.894 1124.6,1642.8 v2(1124.6,1635.4) ; v2(1151.2,1621.3) 1155.2,1617.3 v2(1173.8,1617.3) ; v2(1181.4,1617.4) 1186.295,1622.295 RW19.1@1201.521,1622.295 ; RW19.1@1201.189,1622.012 ccw(c1200.506,1621.329) 1200.506,1622.295 ccw(c1200.506,1623.261) RW19.1@1201.189,1622.578
  BottomLayer w0.2: v2(1124.6,1635.4) 1129.4,1630.6 1132.3,1630.6 1140.8,1622.1 1150.4,1622.1 v2(1151.2,1621.3) ; v2(1173.8,1617.3) v2@1181.4,1617.3
GPC1_2: J1.151
GPC1_3: J1.152 R17.1 | length 121.7
  TopLayer w0.2: 1122.296,1645.728 J1.152@1122.296,1648.506 ; 1122.306,1645.728 1125.3,1642.734 1125.3,1632.9 1127.9,1630.3 1127.9,1596.3 v2(1134.1,1590.1) ; v2(1172,1588.2) 1176.2,1588.2 1184.059,1580.341 R17.1@1186.991,1580.341 ; R17.1@1186.659,1580.059 ccw(c1185.976,1579.376) 1185.976,1580.341 ccw(c1185.976,1581.307) R17.1@1186.659,1580.624
  BottomLayer w0.2: v2(1134.1,1590.1) 1157.5,1590.1 1159.4,1588.2 v2(1172,1588.2)
GPC1_4: J1.153 R18.1 | length 132.4
  TopLayer w0.135: 1122.695,1647.023 1122.695,1650.806 1123.096,1651.206 J1.153@1123.096,1653.706
  TopLayer w0.2: 1122.705,1647.012 1122.705,1645.895 1125.7,1642.9 1125.7,1633.1 1128.3,1630.5 1128.3,1596.9 v2(1134,1591.2) ; v2(1171.5,1589.2) 1175.8,1589.2 1183.7,1581.3 1191.45,1581.3 R18.1@1192.5,1580.25 ; 1191.732,1581.018 cw(c1190.964,1580.25) R18.1@1192.05,1580.25 ; 1191.853,1580.897 ccw(c1192.45,1581.495) R18.1@1192.45,1580.65 ; R18.1@1192.073,1580.677 cw(c1191.646,1580.25) R18.1@1192.25,1580.25
  BottomLayer w0.2: v2(1134,1591.2) 1157.7,1591.2 1159.7,1589.2 v2(1171.5,1589.2)
GPJ0_0: CAMERA_B.16 J1.201 | length 88.5
  TopLayer w0.135: 1136.8,1638 1140.8,1638
  TopLayer w0.2: CAMERA_B.16@1131.8,1571.2 1132.8,1572.2 1132.8,1575.6 1138.5,1581.3 1138.5,1588.266 1129.15,1597.616 1129.15,1628.85 1131.5,1631.2 1131.5,1635.179 1134.316,1637.995 ; CAMERA_B.16@1131.8,1571.5 ccw(c1131.8,1572.224) 1132.312,1571.712 ccw(c1132.824,1571.2) CAMERA_B.16@1132.1,1571.2 ; CAMERA_B.16@1131.8,1571.7 ccw(c1131.8,1572.907) 1132.654,1572.054 ccw(c1133.507,1571.2) CAMERA_B.16@1132.3,1571.2 ; 1134.316,1638 1136.8,1638 ; 1140.8,1638 1141.2,1638.4 J1.201@1143.7,1638.4 ; J1.201@1142.579,1638.329 ccw(c1142.409,1638.159) 1142.409,1638.4 ccw(c1142.409,1638.641) J1.201@1142.579,1638.471
GPJ0_1: CAMERA_B.15 J1.202 | length 81.3
  TopLayer w0.2: CAMERA_B.15@1131.446,1573.554 ccw(c1130.593,1574.407) 1131.8,1574.407 ccw(c1133.007,1574.407) CAMERA_B.15@1132.154,1573.554 ; CAMERA_B.15@1131.588,1573.412 ccw(c1131.076,1573.924) 1131.8,1573.924 ccw(c1132.524,1573.924) CAMERA_B.15@1132.012,1573.412 ; CAMERA_B.15@1131.8,1573.2 1131.8,1575.3 1138.1,1581.6 1138.1,1588.1 1128.75,1597.45 1128.75,1629.05 1131.1,1631.4 1131.1,1635.35 1134.145,1638.395 J1.202@1138.515,1638.395
GPJ0_2: CAMERA_B.14 J1.203 | length 86.8
  TopLayer w0.135: 1136.801,1637.201 1140.686,1637.201 1141.085,1637.6 J1.203@1143.7,1637.6 ; 1142.33,1637.6 ccw(c1142.33,1637.92) J1.203@1142.556,1637.694 ; 1142.33,1637.6 cw(c1142.33,1637.28) J1.203@1142.556,1637.506
  TopLayer w0.2: CAMERA_B.14@1133.8,1571.2 1134.8,1572.2 1134.8,1576.4 1139.3,1580.9 1139.3,1588.597 1129.95,1597.947 1129.95,1628.45 1132.3,1630.8 1132.3,1634.8 1134.695,1637.195 ; CAMERA_B.14@1133.8,1571.5 ccw(c1133.8,1572.224) 1134.312,1571.712 ccw(c1134.824,1571.2) CAMERA_B.14@1134.1,1571.2 ; CAMERA_B.14@1133.8,1571.7 ccw(c1133.8,1572.907) 1134.654,1572.054 ccw(c1135.507,1571.2) CAMERA_B.14@1134.3,1571.2 ; 1134.7,1637.195 1134.7,1637.2 1136.8,1637.2
GPJ0_3: CAMERA_B.13 J1.204 | length 79.5
  TopLayer w0.2: CAMERA_B.13@1133.446,1573.554 ccw(c1132.593,1574.407) 1133.8,1574.407 ccw(c1135.007,1574.407) CAMERA_B.13@1134.154,1573.554 ; CAMERA_B.13@1133.588,1573.412 ccw(c1133.076,1573.924) 1133.8,1573.924 ccw(c1134.524,1573.924) CAMERA_B.13@1134.012,1573.412 ; CAMERA_B.13@1133.8,1573.2 1133.8,1576 1138.9,1581.1 1138.9,1588.431 1129.55,1597.781 1129.55,1628.65 1131.9,1631 1131.9,1635.013 1134.481,1637.595 J1.204@1138.515,1637.595
GPJ0_4: CAMERA_B.12 J1.205 | length 84.9
  TopLayer w0.135: 1136.801,1636.399 1140.638,1636.399 1141.038,1636.8 J1.205@1143.7,1636.8 ; J1.205@1142.556,1636.706 ccw(c1142.33,1636.48) 1142.33,1636.8 ccw(c1142.33,1637.12) J1.205@1142.556,1636.894
  TopLayer w0.2: CAMERA_B.12@1135.8,1571.2 1136.8,1572.2 1136.8,1577.1 1140.1,1580.4 1140.1,1588.928 1130.75,1598.278 1130.75,1628.05 1133.1,1630.4 1133.1,1634.35 1135.145,1636.395 1136.795,1636.395 1136.8,1636.4 ; CAMERA_B.12@1135.8,1571.5 ccw(c1135.8,1572.224) 1136.312,1571.712 ccw(c1136.824,1571.2) CAMERA_B.12@1136.1,1571.2 ; CAMERA_B.12@1135.8,1571.7 ccw(c1135.8,1572.907) 1136.654,1572.054 ccw(c1137.507,1571.2) CAMERA_B.12@1136.3,1571.2
GPJ0_5: CAMERA_B.11 J1.206 | length 77.6
  TopLayer w0.2: CAMERA_B.11@1135.446,1573.554 ccw(c1134.593,1574.407) 1135.8,1574.407 ccw(c1137.007,1574.407) CAMERA_B.11@1136.154,1573.554 ; CAMERA_B.11@1135.588,1573.412 ccw(c1135.076,1573.924) 1135.8,1573.924 ccw(c1136.524,1573.924) CAMERA_B.11@1136.012,1573.412 ; CAMERA_B.11@1135.8,1573.2 1135.8,1576.7 1139.7,1580.6 1139.7,1588.763 1130.35,1598.113 1130.35,1628.25 1132.7,1630.6 1132.7,1634.629 1134.866,1636.795 J1.206@1138.515,1636.795
GPJ0_6: CAMERA_B.10 J1.207 | length 83.1
  TopLayer w0.135: 1136.801,1635.601 1140.648,1635.601 1141.047,1636 J1.207@1143.7,1636 ; J1.207@1142.556,1635.906 ccw(c1142.33,1635.68) 1142.33,1636 ccw(c1142.33,1636.32) J1.207@1142.556,1636.094
  TopLayer w0.2: 1136.8,1635.6 1136.795,1635.595 1135.476,1635.595 1133.9,1634.019 1133.9,1630 1131.55,1627.65 1131.55,1598.61 1140.9,1589.26 1140.9,1579.8 1138.9,1577.8 1138.9,1572.3 CAMERA_B.10@1137.8,1571.2 ; CAMERA_B.10@1137.8,1571.5 ccw(c1137.8,1572.224) 1138.312,1571.712 ccw(c1138.824,1571.2) CAMERA_B.10@1138.1,1571.2 ; CAMERA_B.10@1137.8,1571.7 ccw(c1137.8,1572.907) 1138.654,1572.054 ccw(c1139.507,1571.2) CAMERA_B.10@1138.3,1571.2
GPJ0_7: CAMERA_B.9 J1.208 | length 75.7
  TopLayer w0.2: CAMERA_B.9@1137.446,1573.554 ccw(c1136.593,1574.407) 1137.8,1574.407 ccw(c1139.007,1574.407) CAMERA_B.9@1138.154,1573.554 ; CAMERA_B.9@1137.588,1573.412 ccw(c1137.076,1573.924) 1137.8,1573.924 ccw(c1138.524,1573.924) CAMERA_B.9@1138.012,1573.412 ; CAMERA_B.9@1137.8,1573.2 1137.8,1577.4 1140.5,1580.1 1140.5,1589.094 1131.15,1598.444 1131.15,1627.85 1133.5,1630.2 1133.5,1634.184 1135.31,1635.995 J1.208@1138.515,1635.995
GPJ1_0: CAMERA_B.5 J1.209 | length 79.3
  TopLayer w0.135: 1136.801,1634.799 1140.662,1634.799 1141.064,1635.2 J1.209@1143.7,1635.2 ; J1.209@1142.556,1635.106 ccw(c1142.33,1634.88) 1142.33,1635.2 ccw(c1142.33,1635.52) J1.209@1142.556,1635.294
  TopLayer w0.2: 1136.8,1634.8 1136.795,1634.795 1135.807,1634.795 1134.7,1633.687 1134.7,1629.5 1132.35,1627.15 1132.35,1598.941 1141.7,1589.591 1141.7,1579.3 1140.4,1578 1140.4,1576 1141.8,1574.6 CAMERA_B.5@1141.8,1573.2 ; CAMERA_B.5@1141.446,1573.554 ccw(c1140.834,1574.166) 1141.7,1574.166 ccw(c1142.766,1574.166) CAMERA_B.5@1142.012,1573.412 ; 1141.7,1574.649 ccw(c1143.249,1574.649) CAMERA_B.5@1142.154,1573.554
GPJ1_1: CAMERA_B.7 J1.210 | length 73.9
  TopLayer w0.2: J1.210@1138.515,1635.195 1135.642,1635.195 1134.3,1633.853 1134.3,1629.8 1131.95,1627.45 1131.95,1598.775 1141.3,1589.425 1141.3,1579.6 1139.8,1578.1 CAMERA_B.7@1139.8,1573.2 ; CAMERA_B.7@1139.446,1573.554 ccw(c1138.593,1574.407) 1139.8,1574.407 ccw(c1141.007,1574.407) CAMERA_B.7@1140.154,1573.554 ; CAMERA_B.7@1139.588,1573.412 ccw(c1139.076,1573.924) 1139.8,1573.924 ccw(c1140.524,1573.924) CAMERA_B.7@1140.012,1573.412
GPJ1_2: CAMERA_B.6 J1.211 | length 88.8
  TopLayer w0.135: 1136.8,1634 1140.645,1634 1141.045,1634.4 J1.211@1143.7,1634.4 ; J1.211@1142.556,1634.306 ccw(c1142.33,1634.08) 1142.33,1634.4 ccw(c1142.33,1634.72) J1.211@1142.556,1634.494
  TopLayer w0.2: 1136.795,1633.995 1136.245,1633.995 1135.5,1633.25 1135.5,1629 1133.15,1626.65 1133.15,1599.273 1149.9,1582.523 v2(1149.9,1575.3) v2@1150,1575.2
  BottomLayer w0.2: CAMERA_B.6@1141.8,1571.2 1142.8,1572.2 1142.8,1573.7 1143.3,1574.2 1148.7,1574.2 v2@1149.8,1575.3 ; CAMERA_B.6@1141.8,1571.5 ccw(c1141.8,1572.224) 1142.312,1571.712 ccw(c1142.824,1571.2) CAMERA_B.6@1142.1,1571.2 ; CAMERA_B.6@1141.8,1571.7 ccw(c1141.8,1572.907) 1142.654,1572.054 ccw(c1143.507,1571.2) CAMERA_B.6@1142.3,1571.2
GPJ1_3: J1.212 RMB5.1 RMB6.1 | length 69.2
  TopLayer w0.2: J1.212@1138.515,1634.395 1135.973,1634.395 1135.1,1633.522 1135.1,1629.3 1132.75,1626.95 1132.75,1599.107 1142.1,1589.757 1142.1,1581.3 1143.1,1580.3 RMB5.1@1143.1,1578.5 ; 1142.225,1581.175 ccw(c1142.664,1581.614) RMB6.1@1142.868,1581.028 ; 1142.45,1580.95 ccw(c1142.781,1581.28) RMB6.1@1142.934,1580.839 ; 1142.494,1580.906 cw(c1142.238,1580.65) RMB6.1@1142.6,1580.65 ; RMB6.1@1142.717,1580.267 cw(c1141.793,1579.343) 1143.1,1579.343 ; RMB5.1@1142.817,1578.833 ccw(c1142.134,1579.516) 1143.1,1579.516 ccw(c1144.066,1579.516) RMB5.1@1143.383,1578.833 ; RMB6.1@1142.859,1580.409 cw(c1142.276,1579.826) 1143.1,1579.826 cw(c1143.724,1579.826) RMB6.1@1143.283,1580.267
GPJ1_4: CAMERA_B.8 J1.213 R427.2 | length 175
  TopLayer w0.135: 1137.001,1633.201 1141.011,1633.201 1141.409,1633.6 J1.213@1143.7,1633.6 ; J1.213@1142.556,1633.506 ccw(c1142.33,1633.28) 1142.33,1633.6 ccw(c1142.33,1633.92) J1.213@1142.556,1633.694
  TopLayer w0.2: 1137,1633.195 1137,1633.2 1136.3,1633.2 1135.9,1632.8 1135.9,1628.7 1133.55,1626.35 1133.55,1623.35 1133.55,1599.438 1150.6,1582.388 v2(1150.6,1577) ; J1.213@1143.7,1633.6 1146.8,1633.6 1148.6,1635.4 v2(1148.6,1647.3) ; J1.213@1144.821,1633.529 cw(c1144.991,1633.359) 1144.991,1633.6 cw(c1144.991,1633.841) J1.213@1144.821,1633.671 ; v2(1149.5,1656.9) 1162.9,1656.9 1171.8,1665.8 v2(1173,1665.8) ; v2(1192.3,1651.7) 1195.067,1651.7 R427.2@1195.17,1651.802 ; 1193.907,1651.7 ccw(c1193.907,1653.015) R427.2@1194.837,1652.085 ; 1194.39,1651.7 ccw(c1194.39,1652.532) R427.2@1194.978,1651.944 ; 1194.401,1651.7 cw(c1194.401,1651.084) R427.2@1194.837,1651.52
  BottomLayer w0.2: CAMERA_B.8@1139.8,1571.2 1140.8,1572.2 1140.8,1573.8 1141.6,1574.6 1148.2,1574.6 v2(1150.6,1577) ; CAMERA_B.8@1139.8,1571.5 ccw(c1139.8,1572.224) 1140.312,1571.712 ccw(c1140.824,1571.2) CAMERA_B.8@1140.1,1571.2 ; CAMERA_B.8@1139.8,1571.7 ccw(c1139.8,1572.907) 1140.654,1572.054 ccw(c1141.507,1571.2) CAMERA_B.8@1140.3,1571.2 ; v2(1148.6,1647.3) 1148.6,1656 v2(1149.5,1656.9) ; v2(1173,1665.8) 1178.2,1665.8 v2(1192.3,1651.7)
GPJ1_5: J1.214
GPJ2_0: J1.215 J4.35 RW17.2 | length 89.8
  TopLayer w0.2: J1.215@1143.715,1632.795 v2@1145.295,1632.795 ; J1.215@1144.821,1632.729 cw(c1144.978,1632.572) v2@1144.978,1632.795 ; J1.215@1144.821,1632.871 ccw(c1145.005,1633.055) v2@1145.005,1632.795 ; v2(1151.755,1626.87) 1154.582,1626.87 1155.065,1627.353 v1(1159.815,1627.353) ; J4.35@1156.5,1620.3 1157.1,1620.3 1158.1,1621.3 1160.9,1621.3 1166.5,1626.9 1176.534,1626.9 1181.2,1631.566 1181.2,1635.5 1183.5,1637.8 1194.425,1637.8 1202.73,1646.105 RW17.2@1206.829,1646.105 ; RW17.2@1206.496,1645.822 ccw(c1205.813,1645.139) 1205.813,1646.105 ccw(c1205.813,1647.071) RW17.2@1206.496,1646.388
  BottomLayer w0.2: v2(1145.3,1632.8) 1146.48,1631.62 1148.486,1631.62 1151.755,1628.351 v2(1151.755,1626.87) ; v1@1159.815,1627.285 v2(1163.3,1623.8)
GPJ2_1: J1.216 J4.36 RW18.2 | length 98.5
  TopLayer w0.2: J1.216@1138.4,1632.8 1140.295,1632.8 1140.695,1632.4 v2(1141.6,1632.4) ; v2(1150.714,1626.87) 1151.425,1626.159 1154.735,1626.159 1155.598,1625.295 v1@1159.789,1625.295 ; J4.36@1158.5,1620.3 1160.9,1620.3 1167.1,1626.5 1176.7,1626.5 1181.6,1631.4 1181.6,1635.3 1183.7,1637.4 1194.59,1637.4 1202.49,1645.3 1209.7,1645.3 RW18.2@1210.3,1645.9 ; J4.36@1158.737,1620.063 cw(c1159.309,1619.491) 1159.309,1620.3 cw(c1159.309,1621.109) J4.36@1158.737,1620.537 ; J4.36@1158.878,1619.922 cw(c1159.792,1619.008) 1159.792,1620.3 cw(c1159.792,1621.592) J4.36@1158.878,1620.678 ; 1209.826,1645.426 cw(c1210.302,1644.949) RW18.2@1210.438,1645.609 ; RW18.2@1209.989,1645.589 ccw(c1209.773,1645.805) RW18.2@1210.079,1645.805
  BottomLayer w0.2: v2@1141.578,1632.4 1143.171,1630.807 1148.182,1630.807 1150.714,1628.275 v2(1150.714,1626.87) ; v1(1159.866,1625.295) v2@1162.867,1622.293
  other v2: 1162.893,1622.293
GPS_IO: RN4.2 UART4.6 | length 5.2
  TopLayer w0.2: RN4.2@1187.667,1677.783 ccw(c1186.984,1678.466) 1187.95,1678.466 ccw(c1188.916,1678.466) RN4.2@1188.233,1677.783 ; RN4.2@1187.95,1677.5 1187.95,1679.6 UART4.6@1188.65,1680.3 ; 1188.135,1679.785 cw(c1188.578,1679.341) UART4.6@1188.64,1679.966
HDMI_CEC: HDMI.13 J1.107 RH16.2 | length 63
  TopLayer w0.2: HDMI.13@1049.3,1652.2 1055.4,1652.2 1059.2,1648.4 1070.3,1648.4 1082.9,1661 1093.7,1661 1097.775,1656.925 J1.107@1097.775,1653.687 ; RH16.2@1065.267,1649.417 cw(c1064.584,1648.734) 1065.55,1648.734 cw(c1066.516,1648.734) RH16.2@1065.833,1649.417 ; 1065.55,1648.45 RH16.2@1065.55,1649.7
HDMI_HPD: J1.108 QH1.E RH14.1 | length 55.6
  TopLayer w0.135: J1.108@1097.671,1649.641 ccw(c1097.445,1649.867) 1097.765,1649.867 ccw(c1098.084,1649.867) J1.108@1097.858,1649.641 ; J1.108@1097.765,1648.497 1097.765,1651.18 1098.164,1651.58 1098.164,1655.364
  TopLayer w0.2: RH14.1@1064.002,1649.695 QH1.E@1065.555,1651.248 ; RH14.1@1064.052,1650.095 ccw(c1064.052,1650.94) 1064.649,1650.342 ; RH14.1@1064.252,1649.695 cw(c1064.855,1649.695) RH14.1@1064.429,1650.121 ; RH14.1@1064.452,1649.695 cw(c1065.538,1649.695) 1064.77,1650.463 ; 1064.789,1650.482 ccw(c1064.023,1651.248) QH1.E@1065.106,1651.248 ; 1064.887,1650.58 cw(c1065.514,1649.953) QH1.E@1065.514,1650.84 ; QH1.E@1065.13,1650.823 ccw(c1064.706,1651.248) QH1.E@1065.306,1651.248 ; QH1.E@1065.641,1651.248 1072.351,1651.248 1082.503,1661.4 1093.9,1661.4 1098.169,1657.131 1098.169,1655.369 ; QH1.E@1066.057,1650.959 cw(c1066.753,1650.263) 1066.753,1651.248 cw(c1066.753,1652.233) QH1.E@1066.057,1651.536
HDMI_TX0N: HDMI.9 J1.104 | length 64.3
  TopLayer w0.135: J1.104@1096.071,1649.641 ccw(c1095.845,1649.867) 1096.165,1649.867 ccw(c1096.484,1649.867) J1.104@1096.258,1649.641 ; J1.104@1096.165,1648.497 1096.165,1651.01 1096.564,1651.409 1096.564,1655.195
  TopLayer w0.2: HDMI.9@1049.3,1650.2 1050.8,1650.2 1051.2,1649.8 1054.2,1649.8 1057.6,1646.4 1069.997,1646.4 1083.397,1659.8 1093.1,1659.8 1096.569,1656.331 1096.569,1655.2
HDMI_TX0P: HDMI.7 J1.103 | length 57.7
  TopLayer w0.2: HDMI.7@1049.3,1649.2 1050.8,1649.2 1051,1649.4 1054,1649.4 1057.4,1646 1070.163,1646 1083.563,1659.4 1092.9,1659.4 1096.165,1656.135 J1.103@1096.165,1653.697
HDMI_TX1N: HDMI.6 J1.102 | length 63
  TopLayer w0.135: J1.102@1095.271,1649.641 ccw(c1095.045,1649.867) 1095.365,1649.867 ccw(c1095.684,1649.867) J1.102@1095.458,1649.641 ; J1.102@1095.365,1648.497 1095.365,1651.061 1095.765,1651.461 1095.765,1655.191
  TopLayer w0.2: HDMI.6@1049.3,1648.7 1050.9,1648.7 1051.2,1648.4 1053.8,1648.4 1057,1645.2 1069.928,1645.2 1083.728,1659 1092.7,1659 1095.756,1655.944 1095.756,1655.2
HDMI_TX1P: HDMI.4 J1.101 | length 56.5
  TopLayer w0.2: HDMI.4@1049.3,1647.7 1050.9,1647.7 1051.2,1648 1053.6,1648 1056.8,1644.8 1070.094,1644.8 1083.894,1658.6 1092.5,1658.6 1095.375,1655.725 J1.101@1095.375,1653.687
HDMI_TX2N: HDMI.3 J1.100 | length 61.7
  TopLayer w0.135: J1.100@1094.471,1649.641 ccw(c1094.245,1649.867) 1094.565,1649.867 ccw(c1094.884,1649.867) J1.100@1094.658,1649.641 ; J1.100@1094.565,1648.497 1094.565,1651.07 1094.963,1651.468 1094.963,1655.195
  TopLayer w0.2: HDMI.3@1049.3,1647.2 1050.8,1647.2 1051.2,1646.8 1053.6,1646.8 1056.4,1644 1069.86,1644 1084.06,1658.2 1092.264,1658.2 1094.969,1655.496 1094.969,1655.2
HDMI_TX2P: HDMI.1 J1.99 | length 55.1
  TopLayer w0.2: HDMI.1@1049.3,1646.2 1051,1646.2 1051.2,1646.4 1053.434,1646.4 1056.234,1643.6 1070.025,1643.6 1084.225,1657.8 1092.1,1657.8 1094.575,1655.325 J1.99@1094.575,1653.687 ; J1.99@1094.565,1653.697 J1.99@1094.588,1653.72
HDMI_TXCN: HDMI.12 J1.106 | length 65.6
  TopLayer w0.12: J1.106@1096.965,1648.497 J1.106@1096.965,1648.605
  TopLayer w0.135: J1.106@1096.871,1649.641 ccw(c1096.645,1649.867) 1096.965,1649.867 ccw(c1097.284,1649.867) J1.106@1097.058,1649.641 ; J1.106@1096.965,1648.605 1096.965,1651.042 1097.366,1651.444 1097.366,1655.29
  TopLayer w0.2: HDMI.12@1049.3,1651.7 1050.7,1651.7 1051,1651.4 1054.6,1651.4 1058.4,1647.6 1070.066,1647.6 1083.066,1660.6 1084.034,1660.6 1093.5,1660.6 1097.356,1656.744 1097.356,1655.3
HDMI_TXCP: HDMI.10 J1.105 | length 59.1
  TopLayer w0.2: HDMI.10@1049.3,1650.7 1050.7,1650.7 1051,1651 1054.434,1651 1058.234,1647.2 1070.231,1647.2 1083.231,1660.2 1093.3,1660.2 1096.975,1656.525 J1.105@1096.975,1653.687
HOTPLUG: HDMI.19 RH12.2 | length 16.5
  TopLayer w0.2: HDMI.19@1049.3,1655.2 1050.5,1655.2 1051.1,1655.8 1057.1,1655.8 1058.8,1654.1 1061.146,1654.1 RH12.2@1062.252,1652.995 ; HDMI.19@1050.425,1655.225 ccw(c1050.425,1655.466) 1050.596,1655.296 ; 1061.484,1653.763 cw(c1060.715,1652.995) RH12.2@1061.802,1652.995 ; 1061.604,1653.642 ccw(c1062.202,1654.24) RH12.2@1062.202,1653.395 ; RH12.2@1061.825,1653.421 cw(c1061.398,1652.995) RH12.2@1062.002,1652.995
HPL: C515.2 C523.1 PHONE.2 PHONE.10 R503.2 | length 43.9
  TopLayer w0.5: 1093.976,1687.603 ccw(c1095.735,1689.362) PHONE.10@1095.735,1686.875 ; 1094.412,1687.168 cw(c1093.269,1686.025) PHONE.10@1094.885,1686.025 ; 1094.475,1684.614 ccw(c1093.42,1685.67) PHONE.10@1094.895,1685.896 ; 1094.54,1684.68 cw(c1095.735,1683.485) PHONE.10@1095.735,1685.175 ; 1094.83,1686.75 ccw(c1095.735,1687.655) PHONE.10@1095.735,1686.375 ; 1094.917,1677.883 ccw(c1095.6,1678.566) C523.1@1095.6,1677.6 ; C523.1@1095.4,1677.3 1099.193,1677.3 C515.2@1099.231,1677.262 ; PHONE.10@1095.504,1686.076 1093.826,1687.754 1093.826,1693.62 1095.731,1695.525 ; C523.1@1095.6,1677.2 1094.4,1678.4 1094.4,1684.539 PHONE.10@1095.885,1686.025 ; C523.1@1095.777,1677.123 cw(c1096.204,1676.696) 1096.204,1677.3 cw(c1096.204,1677.904) C523.1@1095.777,1677.477 ; R503.2@1096.923,1677.123 ccw(c1096.496,1676.696) 1096.496,1677.3 ccw(c1096.496,1677.904) R503.2@1096.923,1677.477 ; R503.2@1096.995,1677.3 ccw(c1096.995,1680.118) C515.2@1098.987,1678.125 ; PHONE.2@1097.124,1694.934 ccw(c1095.731,1693.586) 1095.731,1695.525 ; PHONE.2@1097.124,1696.116 cw(c1095.731,1697.463) 1095.731,1695.525 ; R503.2@1097.277,1677.123 cw(c1097.704,1676.696) 1097.704,1677.3 ; R503.2@1097.277,1677.477 ccw(c1097.704,1677.904) 1097.704,1677.3 ; PHONE.2@1097.763,1695.525 1095.731,1695.525 ; 1098.202,1677.3 ccw(c1098.202,1678.91) C515.2@1099.341,1677.772
HPR: C516.2 C522.1 PHONE.3 PHONE.11 R502.2 | length 32.2
  TopLayer w0.5: C522.1@1095.722,1682.521 1099.207,1682.521 C516.2@1099.256,1682.571 ; C522.1@1095.777,1682.373 cw(c1096.134,1682.016) 1096.134,1682.521 ; C522.1@1095.777,1682.727 ccw(c1096.273,1683.223) 1096.273,1682.521 ; PHONE.11@1095.885,1691.825 1098.956,1688.753 C516.2@1098.956,1682.09 ; PHONE.11@1096.035,1690.975 cw(c1096.035,1689.285) PHONE.3@1097.23,1690.48 ; PHONE.11@1096.199,1691.511 ccw(c1097.735,1693.047) PHONE.3@1097.735,1690.875 ; 1096.307,1682.521 ccw(c1096.307,1683.393) R502.2@1096.923,1682.777 ; PHONE.11@1096.32,1691.39 cw(c1094.954,1690.025) PHONE.3@1096.885,1690.025 ; PHONE.11@1096.385,1691.825 ccw(c1097.592,1691.825) 1096.739,1690.971 ; PHONE.11@1096.885,1691.825 ccw(c1099.299,1691.825) PHONE.3@1097.592,1690.118 ; R502.2@1097.277,1682.777 ccw(c1097.893,1683.393) 1097.893,1682.521 ; 1097.689,1682.521 cw(c1097.689,1680.685) C516.2@1098.987,1681.984 ; 1098.104,1682.521 ccw(c1098.104,1683.77) C516.2@1098.987,1682.887 ; PHONE.3@1098.104,1689.177 cw(c1098.174,1688.321) 1098.781,1688.928 cw(c1099.115,1689.262) PHONE.3@1098.73,1689.534 ; 1098.956,1683.936 ccw(c1100.939,1683.936) C516.2@1099.537,1682.534 ; 1098.956,1685.143 ccw(c1102.146,1685.143) C516.2@1099.891,1682.887
HSYNC: J1.77 R107.1 | length 54.4
  TopLayer w0.12: J1.77@1085.198,1637.595 1087.605,1637.595 ; J1.77@1086.349,1637.501 cw(c1086.576,1637.274) 1086.576,1637.595 ; J1.77@1086.349,1637.699 ccw(c1086.6,1637.95) 1086.6,1637.595
  TopLayer w0.135: J1.77@1085.2,1637.6 1087.705,1637.6 1088.103,1637.201 1091.999,1637.201 ; J1.77@1086.344,1637.506 cw(c1086.57,1637.28) 1086.57,1637.6 cw(c1086.57,1637.92) J1.77@1086.344,1637.694
  TopLayer w0.2: 1092.005,1637.195 1097.662,1637.195 1120.36,1614.497 1122.903,1614.497 1124.411,1612.989 R107.1@1124.411,1612 ; R107.1@1124.305,1612.456 ccw(c1124.049,1612.712) 1124.411,1612.712 ccw(c1124.773,1612.712) R107.1@1124.517,1612.456
KP_COL0: J1.27 KEY_6X6.3 RS17.1 | length 173.7
  TopLayer w0.2: KEY_6X6.3@1044,1606 1045.6,1606 1048.6,1609 1048.6,1612.4 1050.2,1614 1075.9,1614 1079.5,1617.6 J1.27@1085.2,1617.6 ; KEY_6X6.3@1044.212,1605.788 cw(c1044.724,1605.276) 1044.724,1606 cw(c1044.724,1606.724) KEY_6X6.3@1044.212,1606.212 ; KEY_6X6.3@1044.354,1605.646 cw(c1045.207,1604.793) 1045.207,1606 cw(c1045.207,1607.207) KEY_6X6.3@1044.354,1606.354
  BottomLayer w0.2: v2(1051,1614) 1054.7,1610.3 1057.663,1610.3 1075.563,1592.4 1095.4,1592.4 1098.1,1595.1 1100,1595.1 1101.5,1593.6 1115,1593.6 1121.8,1586.8 1125.4,1586.8 1131.3,1580.9 1155.5,1580.9 v2(1157.1,1579.3)
KP_COL1: J1.28 KEY_6X6.4 | length 58.8
  TopLayer w0.135: 1083.6,1618 1088.2,1618 1088.6,1617.6 J1.28@1090.4,1617.6 ; J1.28@1089.256,1617.506 ccw(c1089.03,1617.28) 1089.03,1617.6 ccw(c1089.03,1617.92) J1.28@1089.256,1617.694
  TopLayer w0.2: KEY_6X6.4@1042,1606 1043,1607 1045.6,1607 1048.2,1609.6 1048.2,1612.6 1050.35,1614.75 1075.75,1614.75 1079,1618 1083.6,1618 ; KEY_6X6.4@1042,1606.3 ccw(c1042,1607.024) 1042.512,1606.512 ccw(c1043.024,1606) KEY_6X6.4@1042.3,1606 ; KEY_6X6.4@1042,1606.5 ccw(c1042,1607.707) 1042.854,1606.854 ccw(c1043.707,1606) KEY_6X6.4@1042.5,1606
